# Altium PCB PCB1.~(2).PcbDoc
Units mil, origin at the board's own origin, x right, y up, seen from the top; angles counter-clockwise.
Board outline 1575 x 2765 mil, 2 copper layers (Top Layer, Bottom Layer); 14 components, 10 nets, 35 pads, 0 vias.
Unrouted connection lines stored in the file: 4.
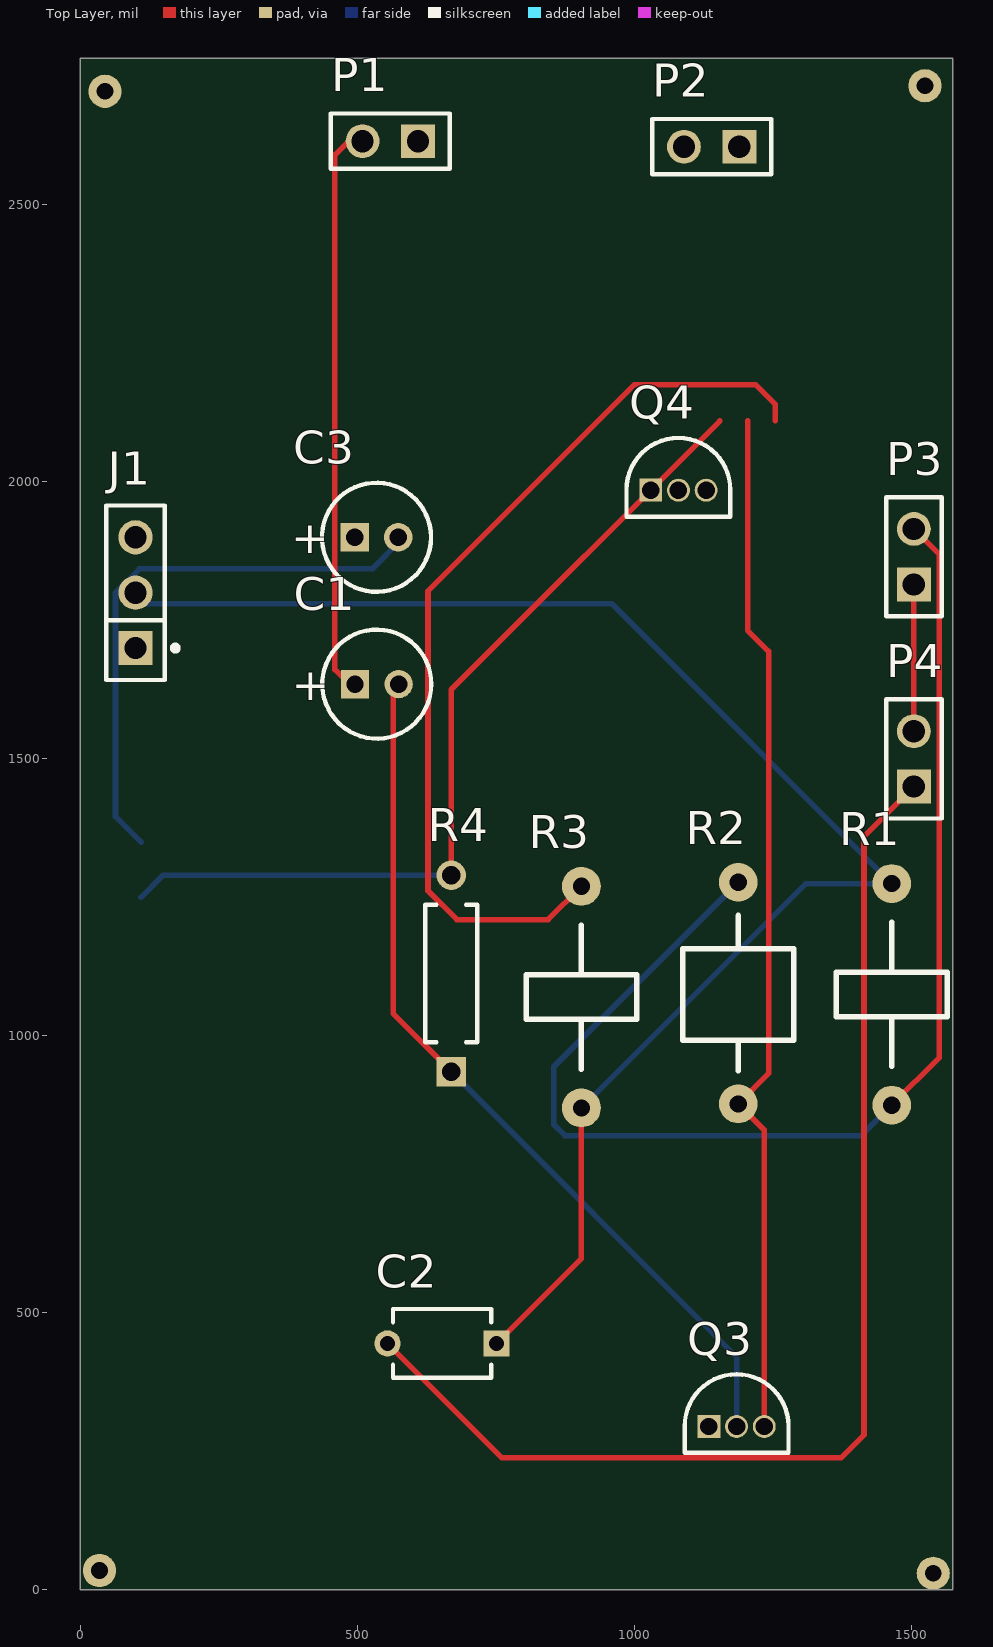
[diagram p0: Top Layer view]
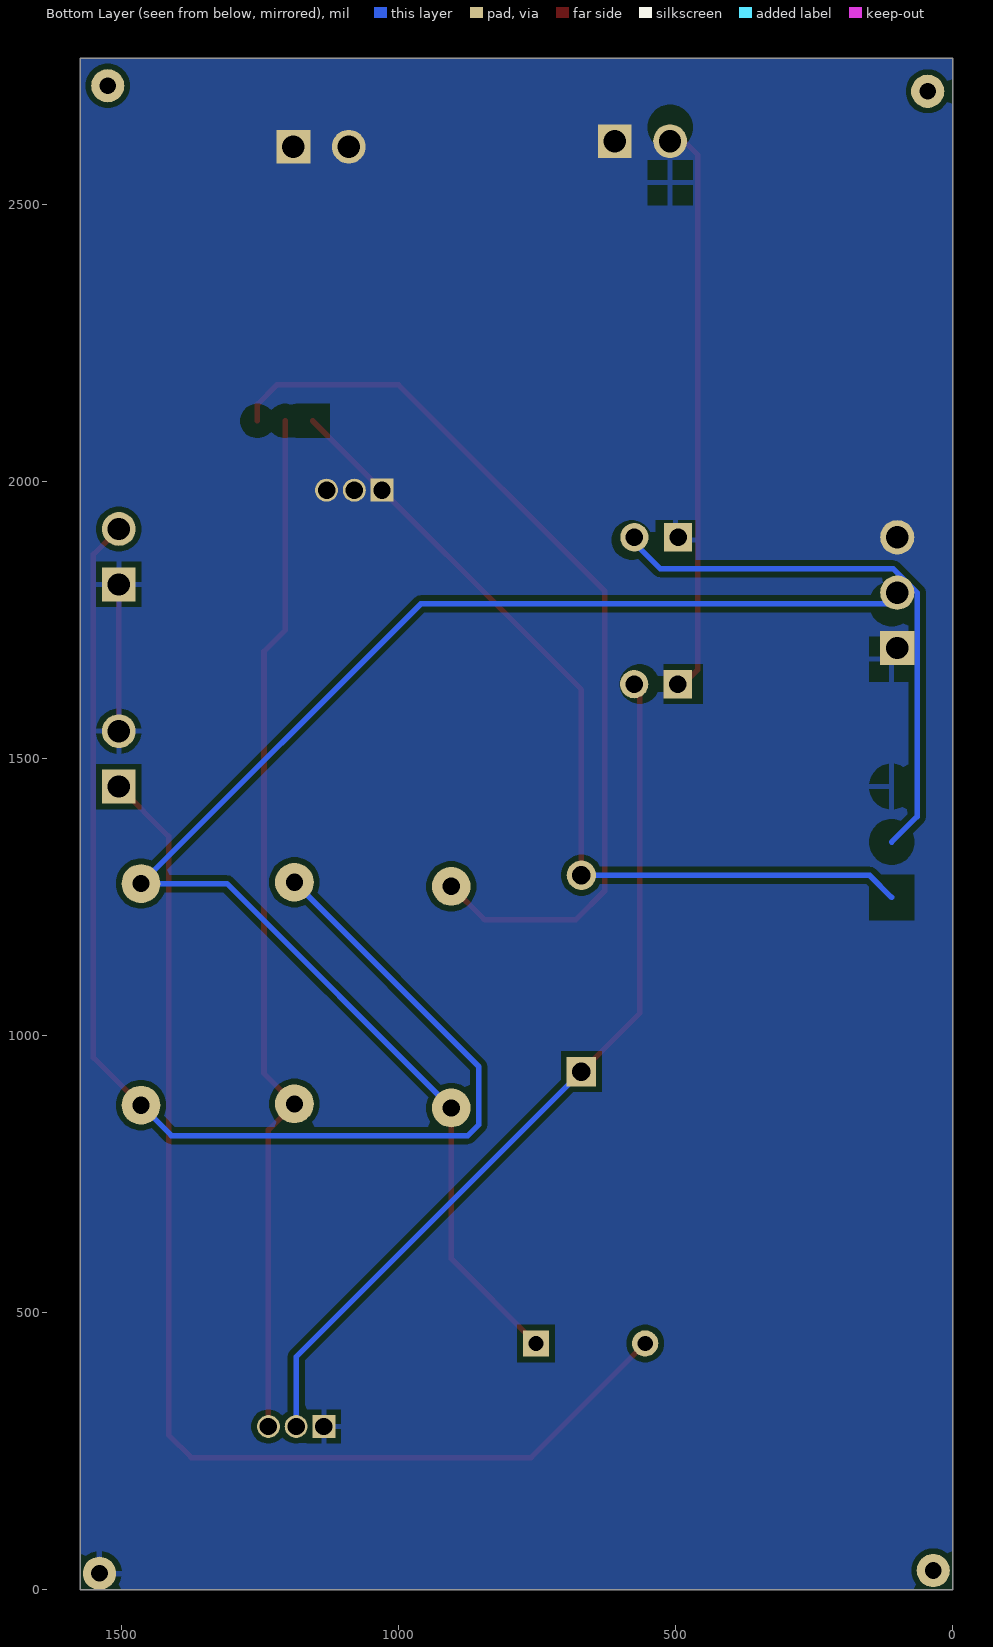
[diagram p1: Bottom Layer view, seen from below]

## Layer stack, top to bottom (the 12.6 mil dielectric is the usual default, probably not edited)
Top Solder: solder mask 0.4, Solder Resist, Dk 3.5
Top Layer: signal copper 1.4
Dielectric 1: dielectric 12.6, FR-4, Dk 4.8
Bottom Layer: signal copper 1.4
Bottom Solder: solder mask 0.4, Solder Resist, Dk 3.5

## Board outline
0,0 1575,0 1575,2765 0,2765

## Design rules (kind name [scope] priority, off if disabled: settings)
Clearance [All] p1: gap=10 ignorepadtopadclearanceinfootprint=FALSE
PolygonConnect [All] p1: connectstyle=Relief reliefconductorwidth=10 reliefentries=4 polygonreliefangle="90 Angle" airgapwidth=10
RoutingVias [All] p1: holewidth=28 width=50 viastyle="Through Hole" minholewidth=28 minwidth=50 maxholewidth=28 maxwidth=50
SolderMaskExpansion [All] p1: expansion=4 istentingtop=FALSE
SupplyNets "Schematic Supply Nets" [InNet('GND')] p1: voltage=0.000
Width [All] p1: maxlimit=10 minlimit=10 preferedwidth=10
30 further rules are at their usual default settings.

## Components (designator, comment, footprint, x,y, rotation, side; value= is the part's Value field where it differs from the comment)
C1 "ECA1HM2R2" CAPPR55-200-1100X500X1200 535.63,1635 r0 top value=2.2µF
C2 "RDER72H103K1K1H03B" FP-RDE1K1-MFG 653.43,445 r180 top
C3 "ECA1HM220" CAPPR55-200-1100X500X1200 535,1900 r0 top value=22µF
J1 "TSW-103-14-G-S" FP-TSW-103-14-G-S-MFG 100,1800 r90 top
P1 "TSW-102-26-G-S" SMTC-TSW-102-26-XX-S 610,2615 r180 top
P2 "TSW-102-26-G-S" SMTC-TSW-102-26-XX-S 1190,2605 r180 top
P3 "TSW-102-26-G-S" SMTC-TSW-102-26-XX-S 1505,1815 r90 top
P4 "TSW-102-26-G-S" SMTC-TSW-102-26-XX-S 1505,1450 r90 top
Q3 "2N3904BU" FAIR-TO-92 1135,295 r0 top
Q4 "2N3904BU" FAIR-TO-92 1030,1985 r0 top
R1 "470 Ohm Generic Resistor" "470 Ohm Resistor" 1465,875 r90 top value=470
R2 "33K Ohm Generic Through Hole Resistor" "Resistor 33K ohm" 1188.07,877.37 r90 top value=33k
R3 "820 Ohm Generic Resistor" "Resistor 820 Ohm Generic" 905,870 r90 top value=820
R4 "MFR-25FBF52-100K" RESA60-630X240 670,1112.83 r90 top value=100k

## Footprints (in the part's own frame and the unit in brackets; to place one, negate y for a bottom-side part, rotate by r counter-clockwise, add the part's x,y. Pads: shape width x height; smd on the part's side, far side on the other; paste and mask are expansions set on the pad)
"470 Ohm Resistor" [mil]
  round 70 hole 31: 1(0,0) 2(400,0)
  silkscreen extent 70,-100 330,100
CAPPR55-200-1100X500X1200 [mm] "THD, 2-Leads, Dia 5mm, Pin Spacing 2mm"
  rect 1.3x1.3 hole 0.8: 1(-1,0)
  round 1.3 hole 0.8: 2(1,0)
  silkscreen extent -2.5,-2.5 2.5,2.5, body extent -2.5,-2.5 2.45,2.5, height 12
FAIR-TO-92 [mm] "TO, 3-Leads, Body Dia 4.79mm, Pitch 1.27mm"
  rect 1.05x1.05 hole 0.8 mask+0.05: 1(0,0)
  round 1.05 hole 0.8 mask+0.05: 2(1.27,0) 3(2.54,0)
  silkscreen extent -1.11,-1.21 3.65,2.4, body extent -1.11,-1.21 3.65,2.4, height 5.33
FP-RDE1K1-MFG [mm]
  rect 1.2x1.2 hole 0.7 paste-2539.97 mask+0: 1(-2.5,0)
  round 1.2 hole 0.7 paste-2539.97 mask+0: 2(2.5,0)
  silkscreen extent -2.25,-1.58 2.25,1.58, body extent -3.2,-1.68 3.2,1.68, height 0.25
FP-TSW-103-14-G-S-MFG [mm]
  rect 1.57x1.57 hole 1.02 paste-2539.97 mask+0: 1(-2.54,0)
  round 1.57 hole 1.02 paste-2539.97 mask+0: 2(0,0) 3(2.54,0)
  silkscreen extent -4,-1.95 4,1.34, body extent -4.1,-1.44 4.1,1.44, height 0.25
RESA60-630X240 [mm] "Axial Resistor, 2-Leads, Dia 2.4mm, Body Length 6.3mm"
  rect 1.35x1.35 hole 0.85: 1(-4.5,0)
  round 1.35 hole 0.85: 2(4.5,0)
  silkscreen extent -3.15,-1.2 3.15,1.2, body extent -4.77,-1.19 4.77,1.2, height 2.4
"Resistor 33K ohm" [mil]
  round 70 hole 31: 1(0,0) 2(400,0)
  silkscreen extent 60,-100 340,100
"Resistor 820 Ohm Generic" [mil]
  round 70 hole 31: 1(0,0) 2(400,0)
  silkscreen extent 70,-100 330,100
SMTC-TSW-102-26-XX-S [mm] ".025 SQ Post Terminal Strip Assembly, 1x2 Pins, Vertical, 2.54mm Pitch, Male"
  rect 1.55x1.55 hole 1.02: 1(0,0)
  round 1.55 hole 1.02: 2(2.54,0)
  silkscreen extent -1.46,-1.27 4,1.27, body extent -1.4,-1.27 3.81,1.27, height 8.38

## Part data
C1: library part CMP-001-00029-7, "Aluminum Electrolytic Capacitor, 2.2 uF, +/- 20%, 50 V, -40 to 85 degC, 2-Pin THD, RoHS, Bulk", Capacitor Type=Electrolytic, Case/Package=Radial, Manufacturer=Panasonic, Max Operating Temperature=85°C, Min Operating Temperature=-40°C, Package Description="2-Pin Radial Lead, Dia 5 mm, Height 12 mm", Package Quantity=200, Package Reference=CAPPR55-200-1100X500X1200, Ripple Current=20mA, Tolerance=20%, Voltage Rating=50V
C2: library part CMP-06035-024341-1, "Ceramic Capacitor 10nF ±10% 500V X7R Radial"
C3: library part CMP-001-00027-7, "Aluminum Electrolytic Capacitor, 22 uF, +/- 20%, 50 V, -40 to 85 degC, 2-Pin THD, RoHS, Bulk", Capacitor Type=Electrolytic, Case/Package=Radial, Manufacturer=Panasonic, Max Operating Temperature=85°C, Min Operating Temperature=-40°C, Package Description="2-Pin Radial Lead, Dia 5 mm, Height 12 mm", Package Quantity=200, Package Reference=CAPPR55-200-1100X500X1200, Ripple Current=100mA, Tolerance=20%, Voltage Rating=50V
J1: library part CMP-02766-001743-1, "CONN HEADER VERT 3POS 2.54MM", Color=Black, Flammability Rating="UL94 V-0", Max Current Rating=7.6A, Max Operating Temperature=125°C, Max Voltage Rating (AC)=550V, Min Operating Temperature=-55°C, Package Quantity=1
P1 P2 P3 P4: library part CMP-1024-00327-1, "0.025\" SQ Post Header, Through-hole, Vertical, -55 to 125 degC, 2.54 mm Pitch, 2-Pin, Male, RoHS", Manufacturer=Samtec, Temperature Range="-55 to 125 degC"
Q3 Q4: library part CMP-2000-04944-1, "NPN General-Purpose Amplifier, 40 V VCEO, 0.2 A, -55 to 150 degC, 2-Pin TO-92, RoHS, Bulk", Manufacturer=FairchildSemiconductor, Maximum Collector Base Voltage=60V, Maximum Collector Emitter Saturation Voltage=0.2@1mA@10mA, Maximum Collector Emitter Voltage=40V, Maximum DC Collector Current=0.2A, Maximum Operating Frequency=300(Min)MHz, Maximum Power Dissipation=625mW, Minimum DC Current Gain=40@0.1mA@1V, Operating Temperature=-55to150degC, Package=3TO-92, Package Description="3-Pin Transistor Outline Package, Body Dia 4.79 mm, Pitch 1.27 mm", Package Reference=TO-92
R1: library part CMP-009-00178-1, Power=250mW
R2: library part CMP-009-00177-1, Power=250mW
R3: library part CMP-009-00179-1, Power=250mW
R4: library part CMP-009-00045-4, "Axial Resistor, 100 KOhm, +/- 1%, 0.25 W, -55 to 155 degC, 2-Pin THD, RoHS, Bulk", Case/Package=Axial, Manufacturer=Yageo, Max Operating Temperature=155°C, Min Operating Temperature=-55°C, Package Description="2-Pin Axial Lead, Dia 2.4 mm, Body Length 6.3 mm", Package Quantity=200, Package Reference=MFR-25, Power=250mW, Tolerance=1%, Voltage Rating=250V

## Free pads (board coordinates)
  round 60 hole 30: 1(45,2705) 2(1525,2715) 3(1540,30) 4(35,35)

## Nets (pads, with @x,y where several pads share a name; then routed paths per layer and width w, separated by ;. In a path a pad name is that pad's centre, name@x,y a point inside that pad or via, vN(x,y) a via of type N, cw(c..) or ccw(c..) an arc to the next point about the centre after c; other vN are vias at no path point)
GND: C3.1 J1.3 P1.1 P2.1 P3.1 P4.2 pad.3 Q3.1 | length 265
  Top Layer w10: P4.2 P3.1
NetC1_1: C1.1 P1.2 | length 1036.6
  Top Layer w10: C1.1@486.26,1635 460,1661.26 460,2590 P1.2@510,2640
NetC1_2: C1.2 Q3.2 R4.1 | length 1596.8
  Top Layer w10: C1.2@565,1635 565,1040.67 R4.1
  Bottom Layer w10: R4.1 1185,420.67 Q3.2
NetC2_1: C2.1 P2.2 R1.2 R3.1 | length 2780.4
  Top Layer w10: C2.1 905,598.15 R3.1
  Bottom Layer w10: 110,1780 960,1780 R1.2 1310,1275 R3.1
NetC2_2: C2.2 P4.1 | length 2169.6
  Top Layer w10: C2.2 761,239 1374,239 1415,280 1415,1360 P4.1
NetC3_2: C3.2 J1.2 | length 1023.8
  Bottom Layer w10: 110,1350 64,1396 64,1800 107,1843 527.37,1843 C3.2@579.37,1895
NetJ1_1: J1.1 Q4.1 R4.2 | length 1597.5
  Top Layer w10: R4.2 670,1625 1155,2110
  Bottom Layer w10: 110,1250 150,1290 R4.2
NetP3_2: P3.2 R1.1 R2.2 | length 2311.1
  Top Layer w10: R1.1 1551,961 1551,1869 P3.2
  Bottom Layer w10: R2.2 855,944.3 855,840 875,820 1410,820 R1.1
NetQ3_3: Q3.3 Q4.2 R2.1 | length 1872.9
  Top Layer w10: 1205,2110 1205,1732 1243,1694 1243,932.3 R2.1 1235,830.44 Q3.3
NetQ4_3: Q4.3 R3.2 | length 1690
  Top Layer w10: R3.2 845,1210 680,1210 628,1262 628,1803 1000,2175 1220,2175 1255,2140 1255,2110

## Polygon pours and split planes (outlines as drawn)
GND on Bottom Layer "GND_L02_P000" (solid, pour order 0): 0,0 1575,0 1575,2765 0,2765 0,2760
